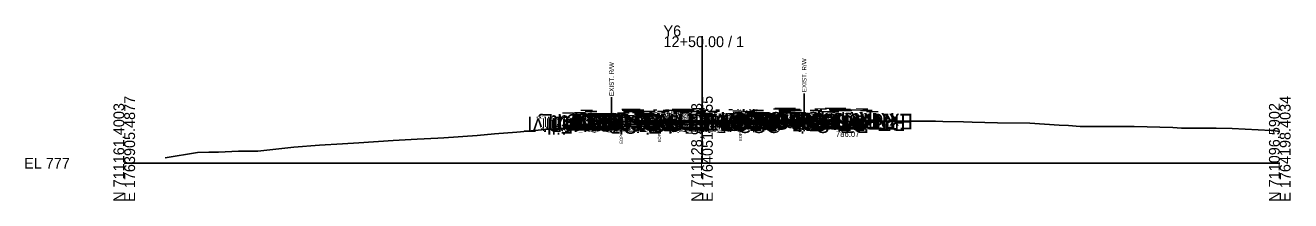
# Model space of a CAD drawing. Extents: x -26 to 1764234, y -10 to 711417.
# Drawn here: x -25.7 to 302.8, y 2490.3 to 2535.8 of the extents above; entities that cross this region are included whole.
import ezdxf

# ---------------------------------------------------------------- set-up
doc = ezdxf.new("R2010")
doc.units = 0
for name, color, linetype in [('Default', 7, 'Continuous'), ('Exist CMT Pavement', 7, 'Continuous'), ('Exist Cross Section Cell', 7, 'Continuous'), ('Exist XS Center Line Elevation Label', 7, 'Continuous'), ('Exist XS Ground Line', 7, 'Continuous'), ('Old_Level_10', 7, 'Continuous'), ('Prop CMT Pvmt Course 1', 7, 'Continuous'), ('Prop CMT Pvmt Course 2', 7, 'Continuous'), ('Prop CMT Pvmt Course 3', 7, 'Continuous'), ('Prop CMT Pvmt Surface', 7, 'Continuous'), ('Prop CMT Pvmt Surface Shoulder', 7, 'Continuous'), ('Prop CMT Shld Paved Course 1', 7, 'Continuous'), ('Prop CMT Shld Paved Course 2', 7, 'Continuous'), ('Prop CMT Shld Paved Course 3', 7, 'Continuous'), ('Prop CMT Slope Grass', 7, 'Continuous'), ('Prop CMT Subgrade Earthwork', 7, 'Continuous'), ('Prop XS Ditch Standard Text', 7, 'Continuous'), ('Prop XS Earthwork Shape', 7, 'Continuous'), ('Prop XS SE Text', 7, 'Continuous'), ('Prop XS Side Slope Text', 7, 'Continuous'), ('Prop XS Wedging', 7, 'Continuous'), ('Scratch_Level_7', 7, 'Continuous')]:
    doc.layers.add(name, color=color, linetype=linetype)

msp = doc.modelspace()

# ---------------------------------------------------------------- linework, layer by layer
at = {"layer": 'Exist CMT Pavement'}
msp.add_lwpolyline([(140.01, 2509.81), (140.36, 2509.88), (141.2, 2509.98), (141.61, 2510.02), (143.33, 2510.04), (144.17, 2510.06), (145.43, 2510.06), (146.73, 2510.06), (147.68, 2510.07), (148.67, 2510.1), (149.44, 2510.12), (150, 2510.12), (151, 2510.14), (151.85, 2510.15), (153.82, 2510.21), (154.41, 2510.23), (155.91, 2510.24), (156.97, 2510.24), (158.63, 2510.26), (159.53, 2510.27), (160, 2510.24)], dxfattribs=at)
at = {"layer": 'Exist Cross Section Cell'}
for p, q in [((150, 2500), (150, 2532.92)), ((0, 2500), (150, 2500)), ((150, 2500), (300, 2500))]:
    msp.add_line(p, q, dxfattribs=at)
at = {"layer": 'Exist XS Ground Line'}
msp.add_lwpolyline([(10.63, 2501.41), (19.04, 2502.78), (21.97, 2502.84), (24.48, 2502.87), (29.7, 2503.17), (32.88, 2503.18), (34.7, 2503.18), (44.03, 2504.16), (50.69, 2504.69), (56.65, 2505.06), (60.93, 2505.27), (69.8, 2505.89), (71.4, 2506.03), (76.01, 2506.26), (81.42, 2506.53), (82.95, 2506.61), (91.66, 2507.24), (96.11, 2507.62), (101.9, 2508.1), (109.26, 2508.77), (112.11, 2508.96), (113.21, 2509.04), (113.83, 2509.08), (114.81, 2509.14), (116.31, 2509.21), (119.37, 2509.37), (128.47, 2509.83), (129.05, 2509.51), (130.57, 2509.51), (131.36, 2509.51), (132.32, 2509.52), (133.92, 2509.55), (135.61, 2509.58), (136.49, 2509.58), (139.05, 2509.86), (139.51, 2509.78), (140.01, 2509.81), (140.36, 2509.88), (141.2, 2509.98), (141.61, 2510.02), (143.33, 2510.04), (144.17, 2510.06), (145.43, 2510.06), (146.73, 2510.06), (147.68, 2510.07), (148.67, 2510.1), (149.44, 2510.12), (150, 2510.12), (151, 2510.14), (151.85, 2510.15), (153.82, 2510.21), (154.41, 2510.23), (155.91, 2510.24), (156.97, 2510.24), (158.63, 2510.26), (159.53, 2510.27), (160.11, 2510.23), (162.2, 2510.14), (162.71, 2510.14), (163.89, 2510.18), (164.99, 2510.29), (166.57, 2510.43), (170.19, 2510.29), (174.88, 2510.49), (176.18, 2510.7), (178.05, 2510.78), (184.28, 2510.86), (184.69, 2510.87), (189.23, 2510.87), (190.27, 2510.97), (192.48, 2510.95), (206.73, 2510.92), (207.12, 2510.92), (207.49, 2510.9), (210.6, 2510.88), (212.51, 2510.84), (217.93, 2510.71), (220.1, 2510.65), (226.71, 2510.47), (235.11, 2510.38), (242.69, 2509.88), (245.15, 2509.83), (248.15, 2509.49), (251.07, 2509.5), (252.49, 2509.54), (262.17, 2509.52), (272.26, 2509.28), (274.51, 2509.13), (282.32, 2509.08), (283.51, 2509.1), (287.66, 2508.98), (294.38, 2508.71), (297.75, 2508.48), (298.17, 2508.49), (300, 2508.26)], dxfattribs=at)
at = {"layer": 'Old_Level_10'}
for p, q in [((126.53, 2517.13), (126.53, 2509.73)), ((176.53, 2518.11), (176.53, 2510.71)), ((160, 2510.24), (160, 2508.19)), ((129.05, 2509.51), (129.05, 2507.46)), ((138.93, 2509.85), (138.93, 2507.8))]:
    msp.add_line(p, q, dxfattribs=at)
at = {"layer": 'Prop CMT Pvmt Course 1'}
for points in [[(150, 2511.13), (135.57, 2511.04)], [(135.57, 2511.04), (135.57, 2510.79)], [(135.57, 2510.79), (140.01, 2510.81)], [(140.01, 2510.81), (150, 2510.88)], [(140.01, 2510.81), (140.01, 2510.81)], [(150, 2511.13), (174, 2511.27)], [(150, 2510.88), (150, 2511.13)], [(160, 2510.94), (150, 2510.88)], [(150, 2510.88), (150, 2510.88), (150, 2510.88)], [(174, 2511.02), (160, 2510.94)], [(160, 2510.94), (160, 2510.94)], [(174, 2511.27), (174, 2511.02)]]:
    msp.add_lwpolyline(points, dxfattribs=at)
at = {"layer": 'Prop CMT Pvmt Course 2'}
for points in [[(140.01, 2510.81), (135.57, 2510.79)], [(135.57, 2510.79), (135.57, 2510.45)], [(135.57, 2510.45), (140.01, 2510.48)], [(140.01, 2510.48), (140.01, 2510.81)], [(160, 2510.94), (174, 2511.02)], [(160, 2510.6), (160, 2510.94)], [(174, 2510.69), (160, 2510.6)], [(174, 2511.02), (174, 2510.69)]]:
    msp.add_lwpolyline(points, dxfattribs=at)
at = {"layer": 'Prop CMT Pvmt Course 3'}
for points in [[(140.01, 2510.48), (135.57, 2510.45)], [(135.57, 2510.45), (135.57, 2510.12)], [(135.57, 2510.12), (140.01, 2510.15)], [(140.01, 2510.15), (140.01, 2510.48)], [(160, 2510.6), (174, 2510.69)], [(160, 2510.27), (160, 2510.6)], [(174, 2510.36), (160, 2510.27)], [(174, 2510.69), (174, 2510.36)]]:
    msp.add_lwpolyline(points, dxfattribs=at)
at = {"layer": 'Prop CMT Pvmt Surface'}
for points in [[(150, 2511.13), (135.57, 2511.04)], [(150, 2511.13), (174, 2511.27)]]:
    msp.add_lwpolyline(points, dxfattribs=at)
at = {"layer": 'Prop CMT Pvmt Surface Shoulder'}
for points in [[(135.57, 2511.04), (133.57, 2511.02)], [(174, 2511.27), (176, 2511.29)]]:
    msp.add_lwpolyline(points, dxfattribs=at)
at = {"layer": 'Prop CMT Shld Paved Course 1'}
for points in [[(135.57, 2511.04), (133.57, 2511.02), (133.32, 2510.77)], [(133.32, 2510.77), (135.57, 2510.79)], [(135.57, 2510.79), (135.57, 2511.04)], [(174, 2511.27), (176, 2511.29), (176.25, 2511.04)], [(174, 2511.02), (174, 2511.27)], [(176.25, 2511.04), (174, 2511.02)]]:
    msp.add_lwpolyline(points, dxfattribs=at)
at = {"layer": 'Prop CMT Shld Paved Course 2'}
for points in [[(135.57, 2510.79), (133.32, 2510.77), (132.98, 2510.44)], [(132.98, 2510.44), (135.57, 2510.45)], [(135.57, 2510.45), (135.57, 2510.79)], [(174, 2511.02), (176.25, 2511.04), (176.58, 2510.71)], [(174, 2510.69), (174, 2511.02)], [(176.58, 2510.71), (174, 2510.69)]]:
    msp.add_lwpolyline(points, dxfattribs=at)
at = {"layer": 'Prop CMT Shld Paved Course 3'}
for points in [[(132.98, 2510.44), (132.65, 2510.1)], [(132.65, 2510.1), (135.57, 2510.12)], [(135.57, 2510.45), (132.98, 2510.44)], [(132.98, 2510.44), (132.98, 2510.44)], [(135.57, 2510.12), (135.57, 2510.45)], [(174, 2510.69), (176.58, 2510.71)], [(174, 2510.36), (174, 2510.69)], [(176.91, 2510.38), (174, 2510.36)], [(176.58, 2510.71), (176.58, 2510.71)], [(176.58, 2510.71), (176.91, 2510.38)]]:
    msp.add_lwpolyline(points, dxfattribs=at)
at = {"layer": 'Prop CMT Slope Grass'}
for points in [[(133.57, 2511.02), (129.57, 2510.76), (125.19, 2509.66)], [(176, 2511.29), (180, 2511.07), (188, 2509.07), (195.48, 2510.94)]]:
    msp.add_lwpolyline(points, dxfattribs=at)
at = {"layer": 'Prop CMT Subgrade Earthwork'}
for p, q in [((140.01, 2510.15), (140.01, 2509.81)), ((160, 2510.27), (160, 2510.24))]:
    msp.add_line(p, q, dxfattribs=at)
for points in [[(132.65, 2510.1), (126.79, 2510.07)], [(135.57, 2510.12), (132.65, 2510.1)], [(140.01, 2510.15), (135.57, 2510.12)], [(160, 2510.27), (174, 2510.36)], [(174, 2510.36), (176.91, 2510.38)], [(176.91, 2510.38), (184.37, 2509.98)]]:
    msp.add_lwpolyline(points, dxfattribs=at)
at = {"layer": 'Prop XS Earthwork Shape'}
for points in [[(139.51, 2509.78), (140.01, 2509.81), (140.01, 2510.15), (135.57, 2510.12), (132.65, 2510.1), (126.79, 2510.07), (125.19, 2509.66), (128.47, 2509.83), (129.05, 2509.51), (130.57, 2509.51), (131.36, 2509.51), (132.32, 2509.52), (133.92, 2509.55), (135.61, 2509.58), (136.49, 2509.58), (139.05, 2509.86)], [(160.11, 2510.23), (162.2, 2510.14), (162.71, 2510.14), (163.89, 2510.18), (164.99, 2510.29), (165.09, 2510.3), (160, 2510.27), (160, 2510.24)], [(165.09, 2510.3), (166.57, 2510.43), (169.14, 2510.33)], [(169.14, 2510.33), (170.19, 2510.29), (171.48, 2510.34)], [(171.48, 2510.34), (174, 2510.36), (176.91, 2510.38), (184.37, 2509.98), (181.02, 2510.82), (178.05, 2510.78), (176.18, 2510.7), (174.88, 2510.49)], [(181.02, 2510.82), (184.28, 2510.86), (184.69, 2510.87), (189.23, 2510.87), (190.27, 2510.97), (192.48, 2510.95), (195.48, 2510.94), (188, 2509.07), (184.37, 2509.98)]]:
    msp.add_lwpolyline(points, close=True, dxfattribs=at)
at = {"layer": 'Prop XS Wedging'}
for p, q in [((139.51, 2510.81), (139.05, 2510.81)), ((139.05, 2510.81), (139.05, 2510.48)), ((139.05, 2510.48), (139.51, 2510.48)), ((140.01, 2510.81), (139.51, 2510.81)), ((139.51, 2510.48), (140.01, 2510.48)), ((140.36, 2510.82), (140.01, 2510.81)), ((140.01, 2510.48), (140.36, 2510.49)), ((140.01, 2510.48), (140.01, 2510.48)), ((141.2, 2510.82), (140.36, 2510.82)), ((140.36, 2510.49), (141.2, 2510.49)), ((141.61, 2510.82), (141.2, 2510.82)), ((143.33, 2510.83), (141.61, 2510.82)), ((143.33, 2510.5), (144.17, 2510.51)), ((144.17, 2510.51), (145.43, 2510.52)), ((146.73, 2510.86), (145.43, 2510.85)), ((147.68, 2510.53), (148.67, 2510.54)), ((149.44, 2510.87), (148.67, 2510.87)), ((148.67, 2510.54), (149.44, 2510.54)), ((150, 2510.88), (149.44, 2510.87)), ((149.44, 2510.54), (150, 2510.55)), ((151, 2510.88), (150, 2510.88)), ((150, 2510.55), (151, 2510.55)), ((151.85, 2510.89), (151, 2510.88)), ((151, 2510.55), (151.85, 2510.56)), ((153.82, 2510.9), (151.85, 2510.89)), ((154.41, 2510.9), (153.82, 2510.9)), ((155.91, 2510.91), (154.41, 2510.9)), ((155.91, 2510.58), (156.97, 2510.59)), ((159.53, 2510.93), (158.63, 2510.93)), ((160, 2510.94), (159.53, 2510.93)), ((160, 2510.61), (160, 2510.94))]:
    msp.add_line(p, q, dxfattribs=at)
for points in [[(139.05, 2509.86), (139.05, 2510.81), (139.51, 2510.81), (140.01, 2510.81), (140.36, 2510.82), (141.2, 2510.82), (141.61, 2510.82), (143.33, 2510.83), (144.17, 2510.84), (145.43, 2510.85), (146.73, 2510.86), (147.68, 2510.86), (148.67, 2510.87), (149.44, 2510.87), (150, 2510.88), (150, 2510.88), (151, 2510.88), (151.85, 2510.89), (153.82, 2510.9), (154.41, 2510.9), (155.91, 2510.91), (156.97, 2510.92), (158.63, 2510.93), (159.53, 2510.93), (160.11, 2510.94), (160.11, 2510.23), (159.53, 2510.27), (158.63, 2510.26), (156.97, 2510.24), (155.91, 2510.24), (154.41, 2510.23), (153.82, 2510.21), (151.85, 2510.15), (151, 2510.14), (150, 2510.12), (150, 2510.12), (149.44, 2510.12), (148.67, 2510.1), (147.68, 2510.07), (146.73, 2510.06), (145.43, 2510.06), (144.17, 2510.06), (143.33, 2510.04), (141.61, 2510.02), (141.2, 2509.98), (140.36, 2509.88), (140.01, 2509.81), (139.51, 2509.78)], [(139.05, 2509.86), (139.05, 2510.48), (139.51, 2510.48), (140.01, 2510.48), (140.36, 2510.49), (141.2, 2510.49), (141.61, 2510.49), (143.33, 2510.5), (144.17, 2510.51), (145.43, 2510.52), (146.73, 2510.53), (147.68, 2510.53), (148.67, 2510.54), (149.44, 2510.54), (150, 2510.55), (150, 2510.55), (151, 2510.55), (151.85, 2510.56), (153.82, 2510.57), (154.41, 2510.57), (155.91, 2510.58), (156.97, 2510.59), (158.63, 2510.6), (159.53, 2510.6), (160.11, 2510.61), (160.11, 2510.23), (159.53, 2510.27), (158.63, 2510.26), (156.97, 2510.24), (155.91, 2510.24), (154.41, 2510.23), (153.82, 2510.21), (151.85, 2510.15), (151, 2510.14), (150, 2510.12), (150, 2510.12), (149.44, 2510.12), (148.67, 2510.1), (147.68, 2510.07), (146.73, 2510.06), (145.43, 2510.06), (144.17, 2510.06), (143.33, 2510.04), (141.61, 2510.02), (141.2, 2509.98), (140.36, 2509.88), (140.01, 2509.81), (139.51, 2509.78)]]:
    msp.add_lwpolyline(points, close=True, dxfattribs=at)
for points in [[(141.2, 2510.49), (141.61, 2510.49), (143.33, 2510.5)], [(145.43, 2510.85), (144.17, 2510.84), (143.33, 2510.83)], [(145.43, 2510.52), (146.73, 2510.53), (147.68, 2510.53)], [(148.67, 2510.87), (147.68, 2510.86), (146.73, 2510.86)], [(151.85, 2510.56), (153.82, 2510.57), (154.41, 2510.57), (155.91, 2510.58)], [(158.63, 2510.93), (156.97, 2510.92), (155.91, 2510.91)], [(156.97, 2510.59), (158.63, 2510.6), (159.53, 2510.6), (160, 2510.61)]]:
    msp.add_lwpolyline(points, dxfattribs=at)

# ---------------------------------------------------------------- texts
at = {"layer": 'Default'}
msp.add_text('-', height=0.0001, dxfattribs=at).set_placement((0, 2500))
at = {"layer": 'Exist Cross Section Cell'}
for s, p in [('Y6', (140, 2532.92)), ('12+50.00 / 1', (140, 2530.12)), ('EL 777', (-26, 2498.6))]:
    msp.add_text(s, height=2.8, dxfattribs=at).set_placement(p)
for s, p in [('E 1763905.4877', (2.8, 2490)), ('E 1764051.9455', (152.8, 2490)), ('E 1764198.4034', (302.8, 2490)), ('N 711161.4003', (0, 2490)), ('N 711128.9953', (150, 2490)), ('N 711096.5902', (300, 2490))]:
    msp.add_text(s, height=2.8, rotation=90, dxfattribs=at).set_placement(p)
at = {"layer": 'Exist XS Center Line Elevation Label'}
msp.add_text('787.12', height=1, dxfattribs=at).set_placement((148.01, 2508.12))
at = {"layer": 'Old_Level_10'}
for s, height, p in [('EXIST. R/W', 1.181, (177.12, 2518.41)), ('EXIST. R/W', 1.181, (127.12, 2517.43)), ('EOP', 0.787, (129.45, 2505.06)), ('EOP', 0.787, (139.32, 2505.4)), ('EOP', 0.787, (160.4, 2505.79))]:
    msp.add_text(s, height=height, rotation=90, dxfattribs=at).set_placement(p)
at = {"layer": 'Prop XS Ditch Standard Text'}
msp.add_text('786.07', height=1.5, dxfattribs=at).set_placement((184.75, 2506.82))
at = {"layer": 'Prop XS SE Text'}
for p in [(140.17, 2512.06), (159.38, 2512.18)]:
    msp.add_text('0.006', height=1.5, rotation=0.3547, dxfattribs=at).set_placement(p)
at = {"layer": 'Prop XS Side Slope Text'}
for rotation, p in [(14.0362, (126.93, 2510.65)), (345.9638, (182.53, 2511.11)), (14.0362, (189.82, 2510.16))]:
    msp.add_text('4:1', height=1.5, rotation=rotation, dxfattribs=at).set_placement(p)
at = {"layer": 'Scratch_Level_7'}
for s, p in [('LT_GS_OS_CTL', (149.19, 2512.76)), ('LT_PS3_Shelf_Out', (157.17, 2512.44)), ('LT_PS1_OEOP', (151.47, 2513.02)), ('LT_PS3_OEOP', (151.92, 2512.44)), ('LT_PS2_OEOP', (152.23, 2512.77)), ('LT_PV1_OEOT', (153.2, 2513.04)), ('LT_PV2_OEOT', (154.21, 2512.79)), ('LT_PV3_OEOT', (154.24, 2512.45)), ('LT_Sub_OEOT', (153.68, 2512.12)), ('LT_PV1_OEEOP', (159.7, 2512.81)), ('LT_PV2_OEEOP', (160.71, 2512.81)), ('LT_PV3_OEEOP', (160.74, 2512.48)), ('LT_Sub_OEEOP', (160.18, 2512.15)), ('RT_PV1_IEEOP', (169.32, 2512.88)), ('LT_PV1_IEEOP', (168.82, 2512.88)), ('RT_PV2_IEEOP', (170.33, 2512.88)), ('LT_PV2_IEEOP', (169.82, 2512.88)), ('PV1_PGL', (160.68, 2513.13)), ('PV2_PGL', (161.68, 2512.88)), ('RT_PV1_OEEOP', (180.2, 2512.94)), ('RT_PV2_OEEOP', (181.21, 2512.94)), ('RT_PV3_OEEOP', (181.24, 2512.6)), ('RT_Sub_OEEOP', (180.68, 2512.27)), ('RT_Sub_Trench_Out', (202.86, 2512.38)), ('RT_PV1_OEOT', (192.14, 2513.27)), ('RT_PS3_Shelf_Out', (201.27, 2512.71)), ('RT_PV2_OEOT', (193.15, 2513.02)), ('RT_PV3_OEOT', (193.18, 2512.69)), ('RT_Sub_OEOT', (192.61, 2512.36)), ('RT_PS1_OEOP', (194.41, 2513.29)), ('RT_PS2_OEOP', (195.66, 2513.04)), ('RT_PS3_OEOP', (196.03, 2512.71)), ('RT_GS_OS_CTL', (200.12, 2513.07)), ('Exterior Boundary', (204.79, 2512.82)), ('RT_Slope_Fill', (198.79, 2512.82)), ('LT_Sub_OSS_DLT', (149.75, 2512.07)), ('Exterior Boundary', (148.96, 2511.66)), ('LT_Sub_Trench_Out', (158.09, 2512.1)), ('LT_Slope_Fill', (142.46, 2511.66)), ('RT_Sub_OSS_DLT', (193.35, 2511.85))]:
    msp.add_text(s, height=4, rotation=180, dxfattribs=at).set_placement(p)

doc.saveas('drawing.dxf')
